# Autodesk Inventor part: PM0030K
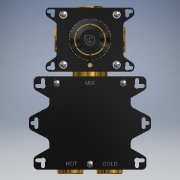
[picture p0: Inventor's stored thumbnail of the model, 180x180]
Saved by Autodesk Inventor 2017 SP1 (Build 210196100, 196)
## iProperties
Created: 2021-08
Part Number: PM0030K
Material: Generico
Document SubType Name: Modeling
Designer: ROSSETTO
Density: 1 g/cm^3
Appearance: Default
Author: ROSSETTO
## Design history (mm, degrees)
feature "Base2"
node "Solido1"
node "Solido3"
